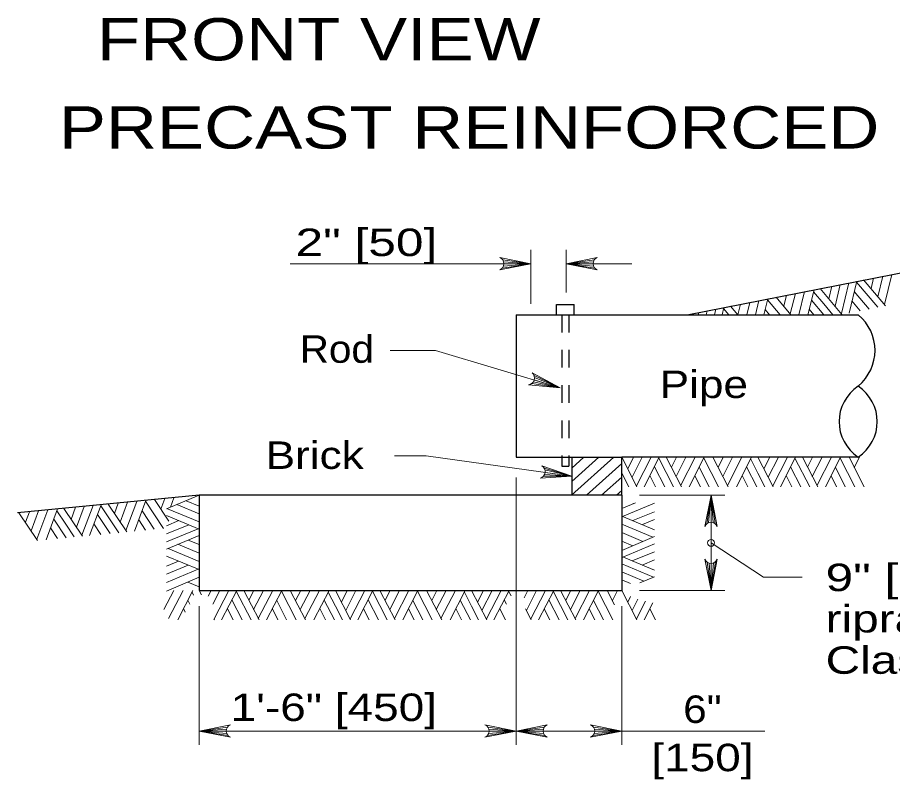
# Model space of a CAD drawing. Extents: x 1083.1 to 1117.1, y 697.4 to 741.4.
# Drawn here: x 1092.416 to 1097.384, y 728.866 to 733.192 of the extents above; entities that cross this region are included whole.
import ezdxf
from ezdxf.enums import TextEntityAlignment as Align

# ---------------------------------------------------------------- set-up
doc = ezdxf.new("R2010")
doc.units = 0
doc.header["$LTSCALE"] = 0.062
doc.linetypes.add('SHORT_DASHED', pattern=[2.7, 1.5, -1.2])
doc.layers.add('1', color=7, linetype='Continuous', lineweight=13)

msp = doc.modelspace()

# ---------------------------------------------------------------- linework, layer by layer
at = {"layer": '1'}
for p, q in [((1095.33067, 731.56733), (1095.33067, 731.87333)), ((1095.53058, 731.63133), (1095.53058, 731.87333)), ((1093.96383, 731.79467), (1095.33067, 731.79467)), ((1095.16858, 731.76992), (1095.33067, 731.79467)), ((1095.17042, 731.81708), (1095.33067, 731.79467)), ((1095.17467, 731.78025), (1095.33067, 731.79467)), ((1095.17592, 731.806), (1095.33067, 731.79467)), ((1095.1775, 731.79467), (1095.33067, 731.79467)), ((1095.69083, 731.81708), (1095.53058, 731.79467)), ((1095.68542, 731.806), (1095.53058, 731.79467)), ((1095.53058, 731.79467), (1095.90383, 731.79467)), ((1095.68375, 731.79467), (1095.53058, 731.79467)), ((1095.68658, 731.78025), (1095.53058, 731.79467)), ((1095.69275, 731.76992), (1095.53058, 731.79467)), ((1097.32883, 731.72367), (1097.30058, 731.60717)), ((1097.38075, 731.73392), (1097.33842, 731.56317)), ((1097.08667, 731.67608), (1097.05742, 731.554)), ((1097.13625, 731.68583), (1097.09358, 731.51167)), ((1097.18133, 731.69475), (1097.13717, 731.5145)), ((1097.17975, 731.68908), (1097.29983, 731.547)), ((1097.21958, 731.70217), (1097.34433, 731.55575)), ((1097.276, 731.71333), (1097.26167, 731.65317)), ((1096.83208, 731.626), (1096.80317, 731.50925)), ((1096.884, 731.63617), (1096.85125, 731.505)), ((1096.93808, 731.64683), (1096.90317, 731.505)), ((1096.93542, 731.63567), (1096.99408, 731.5665)), ((1096.97292, 731.65375), (1097.0965, 731.507)), ((1097.03883, 731.66667), (1097.02183, 731.59592)), ((1097.16692, 731.63717), (1097.25083, 731.53733)), ((1096.57358, 731.57508), (1096.55658, 731.505)), ((1096.6255, 731.58525), (1096.60558, 731.505)), ((1096.67558, 731.59517), (1096.65333, 731.505)), ((1096.6745, 731.59017), (1096.74617, 731.505)), ((1096.72283, 731.60442), (1096.807, 731.505)), ((1096.78092, 731.61583), (1096.76583, 731.554)), ((1096.92342, 731.58767), (1096.99375, 731.505)), ((1097.1535, 731.583), (1097.20008, 731.52742)), ((1096.33142, 731.52742), (1096.326, 731.505)), ((1096.381, 731.53717), (1096.37308, 731.505)), ((1096.42608, 731.54608), (1096.416, 731.505)), ((1096.4245, 731.54042), (1096.45433, 731.505)), ((1096.46433, 731.55358), (1096.50575, 731.505)), ((1096.52067, 731.56467), (1096.50633, 731.5045)), ((1096.66092, 731.53433), (1096.6855, 731.505)), ((1096.91075, 731.53567), (1096.93625, 731.505)), ((1096.99408, 731.5665), (1097.04567, 731.505)), ((1096.28358, 731.518), (1096.28042, 731.505)), ((1095.34492, 731.12408), (1095.49642, 731.09017)), ((1095.34833, 731.16075), (1095.49642, 731.09017)), ((1095.34975, 731.13442), (1095.49642, 731.09017)), ((1095.35125, 731.149), (1095.49642, 731.09017)), ((1095.3365, 731.115), (1095.49642, 731.09017)), ((1095.5465, 730.69542), (1095.54658, 730.6955)), ((1095.56117, 730.47967), (1095.80108, 730.6955)), ((1095.563, 730.63392), (1095.63142, 730.6955)), ((1095.563, 730.55758), (1095.71625, 730.6955)), ((1095.84633, 730.6955), (1095.93225, 730.5285)), ((1095.91383, 730.6955), (1095.88033, 730.62958)), ((1095.96283, 730.6955), (1095.90508, 730.58192)), ((1096.01358, 730.6955), (1095.9305, 730.53358)), ((1096.05967, 730.6955), (1095.97383, 730.52792)), ((1096.05675, 730.69025), (1096.14042, 730.5285)), ((1096.09883, 730.6955), (1096.18592, 730.5285)), ((1096.1565, 730.6955), (1096.12825, 730.6395)), ((1096.21067, 730.6955), (1096.15542, 730.587)), ((1096.26375, 730.6955), (1096.18192, 730.53675)), ((1096.315, 730.6955), (1096.22917, 730.5285)), ((1096.31275, 730.69083), (1096.39642, 730.5285)), ((1096.3635, 730.6955), (1096.45, 730.5285)), ((1096.42292, 730.6955), (1096.3935, 730.63792)), ((1096.47533, 730.6955), (1096.41942, 730.587)), ((1096.52833, 730.6955), (1096.446, 730.53617)), ((1096.58367, 730.6955), (1096.49783, 730.5285)), ((1096.5785, 730.68517), (1096.6195, 730.60625)), ((1096.6195, 730.6955), (1096.70533, 730.5285)), ((1096.687, 730.6955), (1096.6535, 730.62958)), ((1096.73592, 730.6955), (1096.67825, 730.58192)), ((1096.78658, 730.6955), (1096.70367, 730.53358)), ((1096.83275, 730.6955), (1096.74683, 730.52792)), ((1096.82992, 730.69025), (1096.91342, 730.5285)), ((1096.872, 730.6955), (1096.959, 730.5285)), ((1096.92967, 730.6955), (1096.90133, 730.6395)), ((1096.98383, 730.6955), (1096.92842, 730.587)), ((1097.03692, 730.6955), (1096.955, 730.53675)), ((1097.08817, 730.6955), (1097.00233, 730.5285)), ((1097.08583, 730.69083), (1097.16942, 730.5285)), ((1097.13667, 730.6955), (1097.22308, 730.5285)), ((1097.196, 730.6955), (1097.1665, 730.63792)), ((1095.40592, 730.63467), (1095.563, 730.58758)), ((1095.64592, 730.47967), (1095.84633, 730.66)), ((1096.032, 730.64208), (1096.09025, 730.5285)), ((1096.28625, 730.63892), (1096.34275, 730.5285)), ((1096.5555, 730.6405), (1096.61367, 730.5285)), ((1096.80508, 730.64208), (1096.86342, 730.5285)), ((1097.05942, 730.63892), (1097.11583, 730.5285)), ((1095.24667, 730.58167), (1095.24667, 730.448)), ((1095.40117, 730.58767), (1095.563, 730.58758)), ((1095.40808, 730.59792), (1095.563, 730.58758)), ((1095.4105, 730.6235), (1095.563, 730.58758)), ((1095.41133, 730.60892), (1095.563, 730.58758)), ((1095.73083, 730.47967), (1095.84633, 730.58358)), ((1095.84633, 730.60625), (1095.88617, 730.5285)), ((1096.00608, 730.59167), (1096.03833, 730.5285)), ((1096.26208, 730.59017), (1096.29317, 730.5285)), ((1096.53075, 730.59225), (1096.563, 730.5285)), ((1096.6195, 730.60625), (1096.65925, 730.5285)), ((1096.77908, 730.59167), (1096.81142, 730.5285)), ((1097.03508, 730.59017), (1097.06625, 730.5285)), ((1093.4475, 730.47967), (1093.26183, 730.40233)), ((1095.81567, 730.47967), (1095.84633, 730.50725)), ((1095.94633, 730.47967), (1096.43217, 730.47967)), ((1096.32875, 730.3175), (1096.3535, 730.47967)), ((1096.33908, 730.32367), (1096.3535, 730.47967)), ((1096.3535, 730.47967), (1096.3535, 729.93992)), ((1096.3535, 730.3265), (1096.3535, 730.47967)), ((1096.36483, 730.32483), (1096.3535, 730.47967)), ((1096.37592, 730.31942), (1096.3535, 730.47967)), ((1092.92983, 730.42983), (1093.03617, 730.272)), ((1092.98717, 730.43525), (1092.96575, 730.37692)), ((1093.04108, 730.4405), (1092.99883, 730.32733)), ((1093.09375, 730.4455), (1093.03117, 730.27983)), ((1093.14483, 730.4505), (1093.07917, 730.27617)), ((1093.143, 730.44567), (1093.24542, 730.29217)), ((1093.193, 730.45508), (1093.27467, 730.33317)), ((1093.252, 730.46083), (1093.22958, 730.40075)), ((1093.30417, 730.46583), (1093.28375, 730.41192)), ((1093.4475, 730.37483), (1093.32125, 730.42675)), ((1093.4475, 730.41892), (1093.37425, 730.44908)), ((1095.24667, 730.448), (1095.24667, 729.06258)), ((1095.84633, 730.40533), (1095.92425, 730.438)), ((1095.85158, 730.35967), (1096.032, 730.43492)), ((1095.91, 730.4325), (1095.91033, 730.43233)), ((1092.42425, 730.38108), (1092.53, 730.22325)), ((1092.48325, 730.38683), (1092.46083, 730.32675)), ((1092.53542, 730.39175), (1092.49267, 730.27858)), ((1092.58817, 730.39683), (1092.525, 730.23058)), ((1092.64325, 730.40217), (1092.57758, 730.22783)), ((1092.63925, 730.39142), (1092.68933, 730.31683)), ((1092.67875, 730.40558), (1092.78392, 730.24775)), ((1092.74583, 730.41208), (1092.72033, 730.34333)), ((1092.79458, 730.41675), (1092.75075, 730.29817)), ((1092.845, 730.42158), (1092.78158, 730.25267)), ((1092.89083, 730.426), (1092.82525, 730.25117)), ((1092.88867, 730.42058), (1092.99092, 730.26758)), ((1093.12283, 730.3915), (1093.19208, 730.28708)), ((1093.4475, 730.32917), (1093.26758, 730.40392)), ((1095.90925, 730.33583), (1096.032, 730.38658)), ((1092.62167, 730.34483), (1092.69275, 730.23892)), ((1092.86967, 730.37025), (1092.941, 730.26283)), ((1093.10458, 730.34067), (1093.14283, 730.28225)), ((1093.4475, 730.28767), (1093.26125, 730.36492)), ((1093.33217, 730.33592), (1093.26183, 730.30683)), ((1095.84633, 730.36167), (1096.032, 730.28442)), ((1095.96342, 730.314), (1096.032, 730.342)), ((1092.60267, 730.29442), (1092.64233, 730.23408)), ((1092.68933, 730.31683), (1092.73808, 730.24325)), ((1092.84983, 730.31775), (1092.88942, 730.25792)), ((1093.38808, 730.31258), (1093.26183, 730.26017)), ((1093.44167, 730.29025), (1093.26183, 730.215)), ((1095.84633, 730.31558), (1096.02275, 730.24192)), ((1093.4475, 730.25242), (1093.26183, 730.17408)), ((1095.84633, 730.26783), (1095.96692, 730.21808)), ((1095.84633, 730.16717), (1096.032, 730.2455)), ((1093.4475, 730.15175), (1093.32692, 730.2015)), ((1093.4475, 730.2005), (1093.38525, 730.226)), ((1095.84633, 730.21908), (1095.90867, 730.19358)), ((1095.85217, 730.12925), (1096.032, 730.20458)), ((1096.3535, 730.20975), (1096.65108, 730.01458)), ((1093.4475, 730.05783), (1093.26183, 730.13508)), ((1093.4475, 730.104), (1093.27108, 730.17767)), ((1095.84633, 730.13192), (1096.03258, 730.05458)), ((1095.90575, 730.107), (1096.032, 730.15942)), ((1093.33042, 730.1055), (1093.26183, 730.07758)), ((1093.38458, 730.08375), (1093.26183, 730.03292)), ((1095.84633, 730.09042), (1096.02625, 730.01567)), ((1095.96167, 730.08367), (1096.032, 730.11275)), ((1096.33108, 730.10017), (1096.3535, 729.93992)), ((1096.34217, 730.09475), (1096.3535, 729.93992)), ((1096.37833, 730.10208), (1096.3535, 729.93992)), ((1096.36792, 730.09592), (1096.3535, 729.93992)), ((1096.3535, 730.09308), (1096.3535, 729.93992)), ((1093.44225, 730.05992), (1093.26183, 729.98467)), ((1095.84633, 730.04475), (1095.97258, 729.99283)), ((1093.4475, 730.01425), (1093.26183, 729.93642)), ((1093.4475, 729.96083), (1093.3835, 729.98725)), ((1095.84633, 730.00067), (1095.89667, 729.98)), ((1095.94833, 729.98242), (1096.032, 730.01717)), ((1096.65108, 730.01458), (1096.87133, 730.01458)), ((1093.30333, 729.93992), (1093.2475, 729.8315)), ((1093.35642, 729.93992), (1093.274, 729.78067)), ((1093.41167, 729.93992), (1093.32583, 729.77292)), ((1093.4475, 729.93992), (1093.46058, 729.91442)), ((1093.51492, 729.93992), (1093.49833, 729.90742)), ((1093.56392, 729.93992), (1093.52475, 729.86267)), ((1093.61467, 729.93992), (1093.53167, 729.778)), ((1093.66075, 729.93992), (1093.57492, 729.77233)), ((1093.65792, 729.93475), (1093.74158, 729.77292)), ((1093.7, 729.93992), (1093.787, 729.77292)), ((1093.75767, 729.93992), (1093.72933, 729.88392)), ((1093.81183, 729.93992), (1093.7565, 729.8315)), ((1093.86492, 729.93992), (1093.783, 729.78117)), ((1093.91617, 729.93992), (1093.83033, 729.77292)), ((1093.91383, 729.93525), (1093.9975, 729.77292)), ((1093.96467, 729.93992), (1094.05108, 729.77292)), ((1094.024, 729.93992), (1093.99467, 729.88233)), ((1094.0765, 729.93992), (1094.0205, 729.8315)), ((1094.1295, 729.93992), (1094.04708, 729.78067)), ((1094.18483, 729.93992), (1094.099, 729.77292)), ((1094.22058, 729.93992), (1094.3065, 729.77292)), ((1094.28808, 729.93992), (1094.25458, 729.874)), ((1094.33708, 729.93992), (1094.27942, 729.82633)), ((1094.38775, 729.93992), (1094.30475, 729.778)), ((1094.43392, 729.93992), (1094.348, 729.77233)), ((1094.431, 729.93475), (1094.51458, 729.77292)), ((1094.47308, 729.93992), (1094.56017, 729.77292)), ((1094.53075, 729.93992), (1094.5025, 729.88392)), ((1094.58492, 729.93992), (1094.52958, 729.8315)), ((1094.638, 729.93992), (1094.55617, 729.78117)), ((1094.68933, 729.93992), (1094.60342, 729.77292)), ((1094.687, 729.93525), (1094.77058, 729.77292)), ((1094.73775, 729.93992), (1094.82425, 729.77292)), ((1094.79717, 729.93992), (1094.76767, 729.88233)), ((1094.84967, 729.93992), (1094.79367, 729.8315)), ((1094.90258, 729.93992), (1094.82017, 729.78067)), ((1094.958, 729.93992), (1094.872, 729.77292)), ((1094.99367, 729.93992), (1095.07958, 729.77292)), ((1095.06117, 729.93992), (1095.02775, 729.874)), ((1095.11017, 729.93992), (1095.0525, 729.82633)), ((1095.16092, 729.93992), (1095.07792, 729.778)), ((1095.20708, 729.93992), (1095.12108, 729.77233)), ((1095.20417, 729.93475), (1095.21775, 729.90833)), ((1095.31408, 729.93992), (1095.29308, 729.8985)), ((1095.36308, 729.93992), (1095.30542, 729.82633)), ((1095.41383, 729.93992), (1095.33083, 729.778)), ((1095.45992, 729.93992), (1095.37408, 729.77233)), ((1095.457, 729.93475), (1095.54067, 729.77292)), ((1095.49908, 729.93992), (1095.58617, 729.77292)), ((1095.55675, 729.93992), (1095.5285, 729.88392)), ((1095.611, 729.93992), (1095.55567, 729.8315)), ((1095.66408, 729.93992), (1095.58217, 729.78117)), ((1095.71533, 729.93992), (1095.6295, 729.77292)), ((1095.713, 729.93525), (1095.79667, 729.77292)), ((1095.76383, 729.93992), (1095.80617, 729.858)), ((1095.82317, 729.93992), (1095.79375, 729.88233)), ((1095.84633, 729.93992), (1095.93225, 729.77292)), ((1095.94633, 729.93992), (1096.43217, 729.93992)), ((1093.383, 729.88425), (1093.395, 729.86133)), ((1093.4065, 729.92958), (1093.41567, 729.912)), ((1093.63308, 729.8865), (1093.69133, 729.77292)), ((1093.88742, 729.88333), (1093.94383, 729.77292)), ((1094.15667, 729.885), (1094.21483, 729.77292)), ((1094.17967, 729.92958), (1094.22058, 729.85067)), ((1094.40625, 729.8865), (1094.4645, 729.77292)), ((1094.6605, 729.88333), (1094.717, 729.77292)), ((1094.92967, 729.885), (1094.98792, 729.77292)), ((1094.95275, 729.92958), (1094.99367, 729.85067)), ((1095.17933, 729.8865), (1095.19167, 729.8625)), ((1095.43225, 729.8865), (1095.4905, 729.77292)), ((1095.6865, 729.88333), (1095.743, 729.77292)), ((1095.896, 729.90483), (1095.88033, 729.874)), ((1095.93725, 729.88958), (1095.90508, 729.82633)), ((1093.35875, 729.83667), (1093.36858, 729.81717)), ((1093.4475, 729.06258), (1093.4475, 729.85)), ((1093.60725, 729.83617), (1093.6395, 729.77292)), ((1093.86317, 729.83458), (1093.89425, 729.77292)), ((1094.13183, 729.83667), (1094.16417, 729.77292)), ((1094.22058, 729.85067), (1094.26042, 729.77292)), ((1094.38025, 729.83617), (1094.4125, 729.77292)), ((1094.63625, 729.83458), (1094.66742, 729.77292)), ((1094.90492, 729.83667), (1094.93717, 729.77292)), ((1094.99367, 729.85067), (1095.03342, 729.77292)), ((1095.15342, 729.83617), (1095.18567, 729.77292)), ((1095.30017, 729.83575), (1095.3325, 729.77292)), ((1095.40633, 729.83617), (1095.43867, 729.77292)), ((1095.66233, 729.83458), (1095.69342, 729.77292)), ((1095.84633, 729.06258), (1095.84633, 729.85)), ((1095.98217, 729.87867), (1095.9305, 729.778)), ((1096.02375, 729.86983), (1095.97383, 729.77233)), ((1096.00608, 729.83617), (1096.03833, 729.77292)), ((1093.53083, 729.77775), (1093.53333, 729.77292)), ((1093.60775, 729.16367), (1093.4475, 729.14125)), ((1093.60233, 729.15258), (1093.4475, 729.14125)), ((1093.4475, 729.14125), (1095.24667, 729.14125)), ((1093.60067, 729.14125), (1093.4475, 729.14125)), ((1093.6035, 729.12683), (1093.4475, 729.14125)), ((1093.60958, 729.1165), (1093.4475, 729.14125)), ((1095.0845, 729.1165), (1095.24667, 729.14125)), ((1095.08642, 729.16367), (1095.24667, 729.14125)), ((1095.09067, 729.12683), (1095.24667, 729.14125)), ((1095.09183, 729.15258), (1095.24667, 729.14125)), ((1095.0935, 729.14125), (1095.24667, 729.14125)), ((1095.40692, 729.16367), (1095.24667, 729.14125)), ((1095.40142, 729.15258), (1095.24667, 729.14125)), ((1096.65925, 729.14125), (1095.24667, 729.14125)), ((1095.39983, 729.14125), (1095.24667, 729.14125)), ((1095.40267, 729.12683), (1095.24667, 729.14125)), ((1095.40875, 729.1165), (1095.24667, 729.14125)), ((1095.68425, 729.1165), (1095.84633, 729.14125)), ((1095.68608, 729.16367), (1095.84633, 729.14125)), ((1095.69033, 729.12683), (1095.84633, 729.14125)), ((1095.6915, 729.15258), (1095.84633, 729.14125)), ((1095.69317, 729.14125), (1095.84633, 729.14125))]:
    msp.add_line(p, q, dxfattribs=at)
at = {"layer": '1', "lineweight": 25}
for p, q in [((1096.21767, 731.505), (1097.9335, 731.84267)), ((1095.47617, 731.505), (1095.47617, 731.56233)), ((1095.47617, 731.56233), (1095.57608, 731.56233)), ((1095.57608, 731.505), (1095.57608, 731.56233)), ((1095.24667, 731.505), (1097.18875, 731.505)), ((1095.24667, 731.505), (1095.24667, 730.6955)), ((1095.24667, 730.6955), (1095.84633, 730.6955)), ((1095.563, 730.6955), (1095.563, 730.47967)), ((1095.84633, 730.47967), (1095.84633, 730.6955)), ((1097.18875, 730.6955), (1095.84633, 730.6955)), ((1093.4475, 730.47967), (1092.41575, 730.38025)), ((1095.84633, 730.47967), (1093.4475, 730.47967)), ((1095.84633, 730.47967), (1095.84633, 729.93992))]:
    msp.add_line(p, q, dxfattribs=at)
at = {"layer": '1', "linetype": 'SHORT_DASHED', "lineweight": 25}
for p, q in [((1095.50558, 731.505), (1095.50558, 730.64567)), ((1095.5465, 731.505), (1095.5465, 730.64567)), ((1095.50558, 730.64567), (1095.5465, 730.64567))]:
    msp.add_line(p, q, dxfattribs=at)
at = {"layer": '1'}
for points in [[(1095.15367, 731.75925), (1095.33067, 731.79467), (1095.15367, 731.83008)], [(1095.70758, 731.75925), (1095.53058, 731.79467), (1095.70758, 731.83008)], [(1095.49642, 731.09017), (1094.78833, 731.30258), (1094.53092, 731.30258)], [(1095.33717, 731.17517), (1095.49642, 731.09017), (1095.31675, 731.10742)], [(1095.563, 730.58758), (1094.73683, 730.70392), (1094.55667, 730.70392)], [(1095.39267, 730.64725), (1095.563, 730.58758), (1095.38275, 730.57717)], [(1096.31808, 730.30267), (1096.3535, 730.47967), (1096.38892, 730.30267)], [(1096.38892, 730.11692), (1096.3535, 729.93992), (1096.31808, 730.11692)], [(1093.6245, 729.10583), (1093.4475, 729.14125), (1093.6245, 729.17667)], [(1095.06967, 729.10583), (1095.24667, 729.14125), (1095.06967, 729.17667)], [(1095.42367, 729.10583), (1095.24667, 729.14125), (1095.42367, 729.17667)], [(1095.66933, 729.10583), (1095.84633, 729.14125), (1095.66933, 729.17667)]]:
    msp.add_lwpolyline(points, dxfattribs=at)
at = {"layer": '1', "lineweight": 25}
msp.add_lwpolyline([(1093.4475, 730.47967), (1093.4475, 729.93992), (1095.84633, 729.93992)], dxfattribs=at)
at = {"layer": '1'}
msp.add_circle((1096.35351, 730.20978), 0.01967, dxfattribs=at)
for centre, start, end in [((1095.1394, 731.79471), 292.08605, 67.91218), ((1095.7219, 731.79471), 112.08782, 247.91395), ((1095.31326, 731.1454), 275.29169, 51.11782), ((1095.37355, 730.61416), 284.08541, 59.91153), ((1096.35355, 730.28833), 22.08782, 157.91395), ((1096.35347, 730.13123), 202.08782, 337.91395), ((1093.63878, 729.1413), 112.08782, 247.91395), ((1095.05534, 729.1413), 292.08605, 67.91218), ((1095.43793, 729.1413), 112.08782, 247.91395), ((1095.65506, 729.1413), 292.08605, 67.91218)]:
    msp.add_arc(centre, 0.0382, start, end, dxfattribs=at)
at = {"layer": '1', "lineweight": 25}
for centre, major_axis, start_param, end_param in [((1096.97412, 731.30265), (0.31085, 0), 5.4743674, 7.0920031), ((1097.36715, 730.89789), (-0.28709, 0), 5.3830944, 7.1832762), ((1097.36715, 730.89789), (-0.28708, 0), 5.3830944, 7.1832762), ((1097.01029, 730.89789), (0.28708, 0), 5.3830944, 7.1832762)]:
    msp.add_ellipse(centre, major_axis=major_axis, ratio=0.899905, start_param=start_param, end_param=end_param, dxfattribs=at)

# ---------------------------------------------------------------- texts
at = {"layer": '1'}
for s, height, width, p in [('FRONT VIEW', 0.24, 1.25, (1092.86667, 732.94883)), ('PRECAST REINFORCED CONCRETE OUTLET', 0.24, 1.25, (1092.6505, 732.44833)), ('2" [50]', 0.156, 1.35, (1093.99442, 731.838)), ('Rod', 0.156, 1.1, (1094.01825, 731.23208)), ('Pipe', 0.156, 1.2, (1096.06208, 731.03208)), ('Brick', 0.156, 1.2, (1093.82492, 730.62958)), ('9" [225] grouted', 0.156, 1.35, (1097.00375, 729.93583)), ('riprap or 6" [150]', 0.156, 1.3, (1097.00375, 729.70117)), ('Class C concrete', 0.156, 1.3, (1097.00375, 729.4665)), ('1\'-6" [450]', 0.156, 1.25, (1093.62567, 729.19842))]:
    msp.add_text(s, height=height, dxfattribs=dict(at, width=width)).set_placement(p)
for s, width, p in [('6"', 1.15, (1096.3045, 729.18742)), ('[150]', 1.25, (1096.3045, 728.91342))]:
    msp.add_text(s, height=0.156, dxfattribs=dict(at, width=width)).set_placement(p, align=Align.CENTER)

doc.saveas('drawing.dxf')
